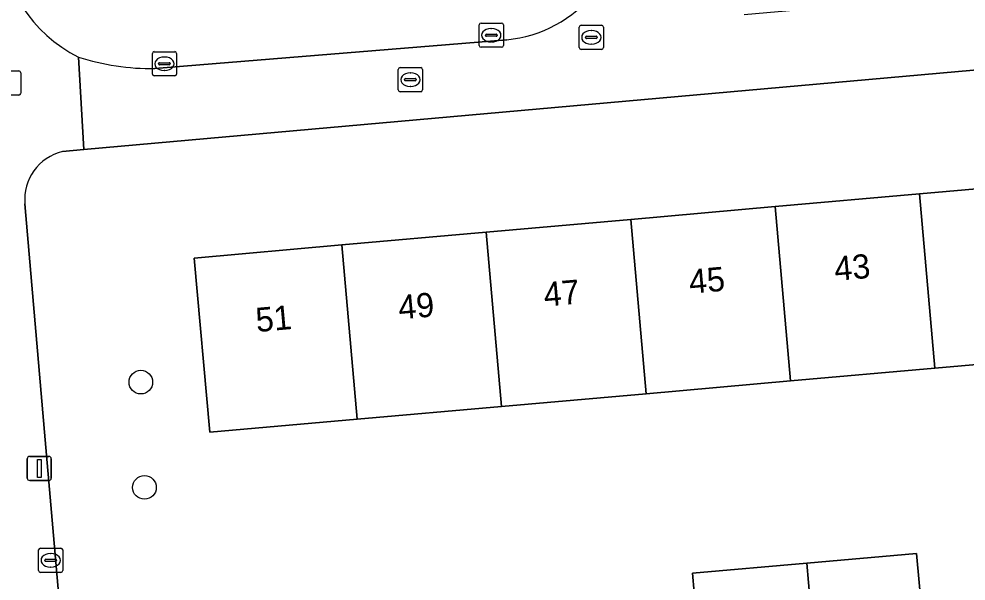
# Model space of a CAD drawing. Extents: x 160554 to 161248, y 385329 to 386506.
# Drawn here: x 160997.31 to 161036.49, y 385493.85 to 385517.1 of the extents above; entities that cross this region are included whole.
import ezdxf

# ---------------------------------------------------------------- set-up
doc = ezdxf.new("R2010")
doc.units = 0
for name, color, linetype in [('IMGEO_Boom', 7, 'Continuous'), ('IMGEO_Brandkraan', 7, 'Continuous'), ('IMGEO_Erf', 7, 'Continuous'), ('IMGEO_Kolk', 7, 'Continuous'), ('IMGEO_Lichtmast', 7, 'Continuous'), ('IMGEO_Pand', 7, 'Continuous'), ('IMGEO_Pand_nummerreeks', 7, 'Continuous'), ('IMGEO_Rijbaan_lokaal_open', 7, 'Continuous'), ('IMGEO_Rioolput', 7, 'Continuous'), ('IMGEO_Voetpad_open', 7, 'Continuous')]:
    doc.layers.add(name, color=color, linetype=linetype)

msp = doc.modelspace()

# ---------------------------------------------------------------- linework, layer by layer
at = {"layer": 'IMGEO_Boom'}
for centre in [(161002.352, 385502.074), (161002.502, 385497.72)]:
    msp.add_circle(centre, 0.489, dxfattribs=at)
at = {"layer": 'IMGEO_Brandkraan'}
for p, q in [((161013.08, 385515.086), (161013.932, 385515.086)), ((161013.005, 385514.16), (161013.005, 385515.012)), ((161013.493, 385514.866), (161013.518, 385514.866)), ((161014.006, 385515.012), (161014.006, 385514.16)), ((161013.264, 385514.58), (161013.264, 385514.592)), ((161013.702, 385514.543), (161013.304, 385514.543)), ((161013.307, 385514.629), (161013.705, 385514.629)), ((161013.516, 385514.306), (161013.491, 385514.306)), ((161013.748, 385514.592), (161013.748, 385514.58)), ((161013.932, 385514.086), (161013.08, 385514.086))]:
    msp.add_line(p, q, dxfattribs=at)
for points in [[(161013.08, 385515.086), (161013.932, 385515.086)], [(161013.005, 385514.16), (161013.005, 385515.012)], [(161014.006, 385515.012), (161014.006, 385514.16)], [(161013.932, 385514.086), (161013.08, 385514.086)]]:
    msp.add_lwpolyline(points, dxfattribs=at)
for centre, radius, start, end in [((161013.082, 385515.01), 0.0765, 91.552, 178.448), ((161013.082, 385515.01), 0.0765, 91.552, 178.448), ((161013.93, 385515.01), 0.0765, 1.552, 88.448), ((161013.93, 385515.01), 0.0765, 1.552, 88.448), ((161013.304, 385514.589), 0.0403, 85.8775, 175.7526), ((161013.301, 385514.579), 0.0366, 178.938, 274.7102), ((161013.705, 385514.586), 0.043, 264.8664, 352.4533), ((161013.709, 385514.591), 0.0386, 1.7309, 96.639), ((161013.082, 385514.162), 0.0765, 181.552, 268.448), ((161013.082, 385514.162), 0.0765, 181.552, 268.448), ((161013.93, 385514.162), 0.0765, 271.552, 358.448), ((161013.93, 385514.162), 0.0765, 271.552, 358.448)]:
    msp.add_arc(centre, radius, start, end, dxfattribs=at)
for centre, major_axis, ratio, start_param, end_param in [((161013.492, 385514.586), (-0.387, 0.002), 0.722429, 4.712389, 7.853982), ((161013.517, 385514.586), (-0.39, 0.002), 0.717154, 1.570796, 4.712389)]:
    msp.add_ellipse(centre, major_axis=major_axis, ratio=ratio, start_param=start_param, end_param=end_param, dxfattribs=at)
at = {"layer": 'IMGEO_Erf'}
for points in [[(161043.347, 385493.291), (161043.14, 385495.666), (161047.927, 385496.087), (161047.288, 385503.716), (161041.186, 385503.177), (161035.209, 385502.649), (161029.232, 385502.122), (161023.256, 385501.594), (161017.279, 385501.066), (161011.302, 385500.538), (161005.206, 385500), (161004.563, 385507.208), (161010.665, 385507.748), (161016.642, 385508.277), (161022.619, 385508.806), (161028.595, 385509.334), (161034.572, 385509.863), (161040.549, 385510.392), (161046.65, 385510.932), (161046.24, 385515.824), (161000, 385511.691), (160999.112, 385511.612)], [(160997.554, 385509.444), (160998.37, 385500), (160999.286, 385489.399)], [(161025.388, 385491.767), (161025.176, 385494.168), (161029.9, 385494.584), (161034.448, 385494.985), (161034.66, 385492.586)]]:
    msp.add_lwpolyline(points, dxfattribs=at)
msp.add_arc((160999.591, 385509.624), 2.045, 103.5371, 185.0582, dxfattribs=at)
at = {"layer": 'IMGEO_Kolk'}
for p, q in [((161016.351, 385515.998), (161016.351, 385516.85)), ((161016.426, 385516.924), (161017.278, 385516.924)), ((161016.839, 385516.704), (161016.864, 385516.704)), ((161017.352, 385516.85), (161017.352, 385515.998)), ((161016.61, 385516.418), (161016.61, 385516.43)), ((161017.048, 385516.381), (161016.65, 385516.381)), ((161016.653, 385516.467), (161017.051, 385516.467)), ((161017.094, 385516.43), (161017.094, 385516.418)), ((161017.278, 385515.924), (161016.426, 385515.924)), ((161016.862, 385516.144), (161016.837, 385516.144)), ((161002.828, 385514.817), (161002.828, 385515.669)), ((161002.903, 385515.743), (161003.755, 385515.743)), ((161003.316, 385515.523), (161003.341, 385515.523)), ((161003.829, 385515.669), (161003.829, 385514.817)), ((161003.087, 385515.237), (161003.087, 385515.249)), ((161003.525, 385515.2), (161003.127, 385515.2)), ((161003.13, 385515.286), (161003.528, 385515.286)), ((161003.571, 385515.249), (161003.571, 385515.237)), ((161003.755, 385514.743), (161002.903, 385514.743)), ((161003.339, 385514.963), (161003.314, 385514.963))]:
    msp.add_line(p, q, dxfattribs=at)
for points in [[(161016.351, 385515.998), (161016.351, 385516.85)], [(161016.426, 385516.924), (161017.278, 385516.924)], [(161017.352, 385516.85), (161017.352, 385515.998)], [(161017.278, 385515.924), (161016.426, 385515.924)], [(161002.828, 385514.817), (161002.828, 385515.669)], [(161002.903, 385515.743), (161003.755, 385515.743)], [(161003.829, 385515.669), (161003.829, 385514.817)], [(161003.755, 385514.743), (161002.903, 385514.743)]]:
    msp.add_lwpolyline(points, dxfattribs=at)
for centre, radius, start, end in [((161016.428, 385516.848), 0.0765, 91.552, 178.448), ((161016.428, 385516.848), 0.0765, 91.552, 178.448), ((161017.276, 385516.848), 0.0765, 1.552, 88.448), ((161017.276, 385516.848), 0.0765, 1.552, 88.448), ((161016.65, 385516.427), 0.0403, 85.8775, 175.7526), ((161016.647, 385516.417), 0.0366, 178.938, 274.7102), ((161017.051, 385516.424), 0.043, 264.8664, 352.4533), ((161017.055, 385516.429), 0.0386, 1.7309, 96.639), ((161016.428, 385516), 0.0765, 181.552, 268.448), ((161016.428, 385516), 0.0765, 181.552, 268.448), ((161017.276, 385516), 0.0765, 271.552, 358.448), ((161017.276, 385516), 0.0765, 271.552, 358.448), ((161002.905, 385515.667), 0.0765, 91.552, 178.448), ((161002.905, 385515.667), 0.0765, 91.552, 178.448), ((161003.753, 385515.667), 0.0765, 1.552, 88.448), ((161003.753, 385515.667), 0.0765, 1.552, 88.448), ((161003.127, 385515.246), 0.0403, 85.8775, 175.7526), ((161003.124, 385515.236), 0.0366, 178.938, 274.7102), ((161003.528, 385515.243), 0.043, 264.8664, 352.4533), ((161003.532, 385515.248), 0.0386, 1.7309, 96.639), ((161002.905, 385514.819), 0.0765, 181.552, 268.448), ((161002.905, 385514.819), 0.0765, 181.552, 268.448), ((161003.753, 385514.819), 0.0765, 271.552, 358.448), ((161003.753, 385514.819), 0.0765, 271.552, 358.448)]:
    msp.add_arc(centre, radius, start, end, dxfattribs=at)
for centre, major_axis, ratio, start_param, end_param in [((161016.838, 385516.424), (-0.387, 0.002), 0.722429, 4.712389, 7.853982), ((161016.863, 385516.424), (-0.39, 0.002), 0.717154, 1.570796, 4.712389), ((161003.315, 385515.243), (-0.387, 0.002), 0.722429, 4.712389, 7.853982), ((161003.34, 385515.243), (-0.39, 0.002), 0.717154, 1.570796, 4.712389)]:
    msp.add_ellipse(centre, major_axis=major_axis, ratio=ratio, start_param=start_param, end_param=end_param, dxfattribs=at)
at = {"layer": 'IMGEO_Lichtmast'}
for p, q in [((160997.754, 385499.005), (160998.544, 385499.005)), ((160998.544, 385499.005), (160997.754, 385499.005)), ((160997.654, 385498.105), (160997.654, 385498.905)), ((160997.654, 385498.905), (160997.654, 385498.105)), ((160998.644, 385498.905), (160998.644, 385498.105)), ((160998.644, 385498.105), (160998.644, 385498.905)), ((160998.544, 385498.005), (160997.754, 385498.005)), ((160997.754, 385498.005), (160998.544, 385498.005))]:
    msp.add_line(p, q, dxfattribs=at)
msp.add_lwpolyline([(160998.074, 385498.88), (160998.224, 385498.88), (160998.224, 385498.13), (160998.074, 385498.13), (160998.074, 385498.88)], dxfattribs=at)
for centre, start, end in [((160997.754, 385498.905), 90, 180), ((160997.754, 385498.905), 90, 180), ((160998.544, 385498.905), 0, 90), ((160998.544, 385498.905), 360, 90), ((160997.754, 385498.105), 180, 270), ((160997.754, 385498.105), 180, 270), ((160998.544, 385498.105), 270, 0), ((160998.544, 385498.105), 270, 0)]:
    msp.add_arc(centre, 0.1, start, end, dxfattribs=at)
at = {"layer": 'IMGEO_Pand'}
for points in [[(161035.209, 385502.649), (161041.186, 385503.177), (161040.549, 385510.392), (161034.572, 385509.863)], [(161034.572, 385509.863), (161028.595, 385509.334), (161029.232, 385502.122), (161035.209, 385502.649)], [(161023.256, 385501.594), (161029.232, 385502.122), (161028.595, 385509.334), (161022.619, 385508.806)], [(161022.619, 385508.806), (161016.642, 385508.277), (161017.279, 385501.066), (161023.256, 385501.594)], [(161016.642, 385508.277), (161010.665, 385507.748), (161011.302, 385500.538), (161017.279, 385501.066)], [(161010.665, 385507.748), (161004.563, 385507.208), (161005.206, 385500), (161011.302, 385500.538)], [(161034.66, 385492.586), (161034.448, 385494.985), (161029.9, 385494.584), (161030.112, 385492.184)], [(161030.112, 385492.184), (161029.9, 385494.584), (161025.176, 385494.168), (161025.388, 385491.767)]]:
    msp.add_lwpolyline(points, close=True, dxfattribs=at)
at = {"layer": 'IMGEO_Rijbaan_lokaal_open'}
msp.add_lwpolyline([(161002.929, 385515.042), (161017.496, 385516.237)], dxfattribs=at)
for centre, radius, start, end in [((161017.008, 385521.483), 5.269, 275.3199, 7.6688), ((161002.387, 385520.786), 5.88, 182.1925, 243.5454), ((161002.848, 385525.158), 10.117, 252.2738, 270.4573)]:
    msp.add_arc(centre, radius, start, end, dxfattribs=at)
at = {"layer": 'IMGEO_Rioolput'}
for p, q in [((161020.491, 385515.91), (161020.491, 385516.762)), ((161020.566, 385516.836), (161021.418, 385516.836)), ((161020.979, 385516.616), (161021.004, 385516.616)), ((161021.492, 385516.762), (161021.492, 385515.91)), ((161020.75, 385516.33), (161020.75, 385516.342)), ((161021.188, 385516.293), (161020.79, 385516.293)), ((161020.793, 385516.379), (161021.191, 385516.379)), ((161021.234, 385516.342), (161021.234, 385516.33)), ((161021.418, 385515.836), (161020.566, 385515.836)), ((161021.002, 385516.056), (161020.977, 385516.056)), ((160996.457, 385514.946), (160997.309, 385514.946)), ((160997.383, 385514.872), (160997.383, 385514.02)), ((160997.309, 385513.946), (160996.457, 385513.946)), ((160998.122, 385494.279), (160998.122, 385495.131)), ((160998.197, 385495.205), (160999.049, 385495.205)), ((160999.123, 385495.131), (160999.123, 385494.279)), ((160998.381, 385494.699), (160998.381, 385494.711)), ((160998.424, 385494.748), (160998.822, 385494.748)), ((160998.61, 385494.985), (160998.635, 385494.985)), ((160998.865, 385494.711), (160998.865, 385494.699)), ((160998.819, 385494.662), (160998.421, 385494.662)), ((160998.633, 385494.425), (160998.608, 385494.425)), ((160999.049, 385494.205), (160998.197, 385494.205))]:
    msp.add_line(p, q, dxfattribs=at)
for points in [[(161020.491, 385515.91), (161020.491, 385516.762)], [(161020.566, 385516.836), (161021.418, 385516.836)], [(161021.492, 385516.762), (161021.492, 385515.91)], [(161021.418, 385515.836), (161020.566, 385515.836)], [(160996.457, 385514.946), (160997.309, 385514.946)], [(160997.383, 385514.872), (160997.383, 385514.02)], [(160997.309, 385513.946), (160996.457, 385513.946)], [(160998.122, 385494.279), (160998.122, 385495.131)], [(160998.197, 385495.205), (160999.049, 385495.205)], [(160999.123, 385495.131), (160999.123, 385494.279)], [(160999.049, 385494.205), (160998.197, 385494.205)]]:
    msp.add_lwpolyline(points, dxfattribs=at)
for centre, radius, start, end in [((161020.568, 385516.76), 0.0765, 91.552, 178.448), ((161020.568, 385516.76), 0.0765, 91.552, 178.448), ((161021.416, 385516.76), 0.0765, 1.552, 88.448), ((161021.416, 385516.76), 0.0765, 1.552, 88.448), ((161020.79, 385516.339), 0.0403, 85.8775, 175.7526), ((161020.787, 385516.329), 0.0366, 178.938, 274.7102), ((161021.191, 385516.336), 0.043, 264.8664, 352.4533), ((161021.195, 385516.341), 0.0386, 1.7309, 96.639), ((161020.568, 385515.912), 0.0765, 181.552, 268.448), ((161020.568, 385515.912), 0.0765, 181.552, 268.448), ((161021.416, 385515.912), 0.0765, 271.552, 358.448), ((161021.416, 385515.912), 0.0765, 271.552, 358.448), ((160997.307, 385514.87), 0.0765, 1.552, 88.448), ((160997.307, 385514.87), 0.0765, 1.552, 88.448), ((160997.307, 385514.022), 0.0765, 271.552, 358.448), ((160997.307, 385514.022), 0.0765, 271.552, 358.448), ((160998.199, 385495.129), 0.0765, 91.552, 178.448), ((160998.199, 385495.129), 0.0765, 91.552, 178.448), ((160999.047, 385495.129), 0.0765, 1.552, 88.448), ((160999.047, 385495.129), 0.0765, 1.552, 88.448), ((160998.421, 385494.708), 0.0403, 85.8775, 175.7526), ((160998.418, 385494.698), 0.0366, 178.938, 274.7102), ((160998.822, 385494.705), 0.043, 264.8664, 352.4533), ((160998.826, 385494.71), 0.0386, 1.7309, 96.639), ((160998.199, 385494.281), 0.0765, 181.552, 268.448), ((160998.199, 385494.281), 0.0765, 181.552, 268.448), ((160999.047, 385494.281), 0.0765, 271.552, 358.448), ((160999.047, 385494.281), 0.0765, 271.552, 358.448)]:
    msp.add_arc(centre, radius, start, end, dxfattribs=at)
for centre, major_axis, ratio, start_param, end_param in [((161020.978, 385516.336), (-0.387, 0.002), 0.722429, 4.712389, 7.853982), ((161021.003, 385516.336), (-0.39, 0.002), 0.717154, 1.570796, 4.712389), ((160998.609, 385494.705), (-0.387, 0.002), 0.722429, 4.712389, 7.853982), ((160998.634, 385494.705), (-0.39, 0.002), 0.717154, 1.570796, 4.712389)]:
    msp.add_ellipse(centre, major_axis=major_axis, ratio=ratio, start_param=start_param, end_param=end_param, dxfattribs=at)
at = {"layer": 'IMGEO_Voetpad_open'}
for points in [[(160985.493, 385610.427), (160987.439, 385588.591), (160987.689, 385585.785), (160987.694, 385585.726), (160987.83, 385584.198), (160988.096, 385581.219), (160989.686, 385563.373), (160989.697, 385563.317), (160990.469, 385555.011), (160990.465, 385554.835), (160995.24, 385500), (160996.184, 385489.155), (160999.286, 385489.399), (160998.37, 385500), (160997.554, 385509.444)], [(160999.768, 385515.522), (161000, 385511.691), (161046.24, 385515.824), (161045.951, 385518.924), (161027.313, 385517.272)], [(161017.496, 385516.237), (161002.929, 385515.042)], [(160999.112, 385511.612), (161000, 385511.691), (160999.768, 385515.522)]]:
    msp.add_lwpolyline(points, dxfattribs=at)
for centre, radius, start, end in [((161017.008, 385521.483), 5.269, 275.3199, 7.6688), ((161002.387, 385520.786), 5.88, 182.1925, 243.5454), ((161002.848, 385525.158), 10.117, 252.2738, 270.4573), ((160999.591, 385509.624), 2.045, 103.5371, 185.0582)]:
    msp.add_arc(centre, radius, start, end, dxfattribs=at)

# ---------------------------------------------------------------- texts
at = {"layer": 'IMGEO_Pand_nummerreeks'}
for s, p in [('43', (161031.085, 385506.261)), ('45', (161025.072, 385505.729)), ('47', (161019.06, 385505.197)), ('49', (161013.047, 385504.665)), ('51', (161007.148, 385504.143))]:
    msp.add_text(s, height=1, rotation=5.0566, dxfattribs=at).set_placement(p)

doc.saveas('drawing.dxf')
